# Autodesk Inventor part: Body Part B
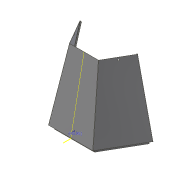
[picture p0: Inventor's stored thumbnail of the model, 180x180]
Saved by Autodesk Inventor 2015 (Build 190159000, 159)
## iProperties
Created: 2013-06
Part Number: Body Part B
Material: Steel, Mild
Document SubType Name: Sheet Metal
Designer: 1103005
Density: 1 g/cm^3
Sheet Metal Rule: Default_mm
Flat Pattern Width: 78.9104 cm
Flat Pattern Length: 65.539 cm
Flat Pattern Area: 5171.71 cm^2
Sheet Metal Width: 789.104 mm
Sheet Metal Length: 655.390 mm
Sheet Metal Area: 517171.389 mm^2
Appearance: Steel
Author: 1103005
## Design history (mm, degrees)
sketch "Sketch1"
  geometry: L1 (277.128, 0)-(138.564, -240); L2 (138.564, -240)-(-138.564, -240); L3 (-138.564, -240)-(-277.128, 0); 3 further points
  constraints: 6 end point, 2 horizontal alignment, 1 coincident, 1 midpoint, 1 vertical alignment, 6 other
  dimensions: "d0" = 240 distance from line of point (0, 0) L2
workplane "Work Plane1"
node "Lofted Flange1"
  sketch "Sketch2"
    geometry: L1 (-138.564, -240)-(-277.128, 0) reference; L2 (138.564, -240)-(-138.564, -240) reference; L3 (277.128, 0)-(138.564, -240) reference; L4 (-90.644, -157)-(-181.288, 0); L5 (181.288, 0)-(90.644, -157); L6 (90.644, -157)-(-90.644, -157); 3 further points
    constraints: 6 end point, 2 horizontal alignment, 1 coincident, 1 midpoint, 1 vertical alignment, 6 other
    dimensions: "d2" = 157 distance from line of point (0, 0) L6
sketch "Sketch13"
  geometry: L1 (0.589, -0.23)-(0, 0) reference; L2 (-155.822, 424.77)-(-238.822, -0.23) reference; L3 (-155.822, 424.77)-(-238.822, -0.23) reference; L4 (-286.704, 0)-(48.471, 0) reference
  dimensions: "Flange_Angle_1" = 78.9496 deg angle of L2 L4 (derived)
  node "Projected Loop1"
node "Flange6"
sketch "Sketch16"
  geometry: L1 (22.086, -274.868)-(22.086, 0) reference; L2 (22.086, 0)-(0, 0) reference; L3 (0, 0)-(0, -262.117) reference; L4 (22.086, -274.868)-(0, -262.117) reference; L5 (-59.178, -47.92)-(23.264, -0.322) reference; L6 (-371.411, -228.188)-(-453.853, -275.786) reference; L7 (-215.5, -386.536)-(-442.5, -255.477) reference; L8 (-442.5, -255.477)-(-454.264, -275.853); L9 (-430.589, -262.354)-(-454.264, -275.853); L10 (0, -13.754)-(23.528, 0); L11 (0, 0)-(23.528, 0); 1 further point
  constraints: 8 end point, 4 point on line, 1 horizontal, 1 other
extrude "Extrusion1" cut sketch "Sketch16" stored distance "d106" = 10; taper "d107" = 0 deg
node "Unfold1"
node "Flange10"
sketch "Sketch22"
  geometry: L1 (5.843, 432.74)-(5.843, 432.28) reference; L2 (0, 432.74)-(5.843, 432.74) reference; L3 (0, 0)-(0, 432.74) reference; L4 (5.843, 432.28)-(0, 430.987); L5 (0, 0)-(0, 432.74) reference; L6 (-126.727, 402.479)-(7.922, 432.28) reference; 1 further point
  constraints: 2 end point, 1 parallel, 1 point on line
cut "Cut3" sketch "Sketch22" dims "d144" = 1.2 (= Thickness), "d145" = 0
mirror "Mirror3"
mirror "Mirror4"
node "Refold1"
node "Flange8"
sketch "Sketch23"
  geometry: L1 (83.554, 224.895)-(1.2, 272.442) reference; L2 (-2.356, 274.546)-(-2.356, 270.364) reference; L3 (-2.356, 281.704)-(83.554, 224.895); L4 (-2.356, 270.364)-(-3.861, 270.364); L5 (-3.861, 270.364)-(-2.356, 281.704); 3 further points; 1 other entity
  constraints: 6 end point, 1 horizontal, 1 other
extrude "Extrusion4" cut sketch "Sketch23" stored distance "d146" = 0; taper "d147" = 0 deg
mirror "Mirror5"
sketch "Sketch24"
  geometry: 3 further points; 1 other entity
  constraints: 1 coincident, 1 other
hole "Hole2" sketch "Sketch24" at (13.533, 89.284) diameter "d148" = 7.5; stored, may be unused: countersink angle "d152" = 90 deg, drill point angle "d154" = 118 deg; dims "d149" = 6, "d150" = 4, "d151" = 2, "d153" = 1.2 (= Thickness)
pattern_circular "Circular Pattern2" dims angle "d156" = 120 deg
body "Solid1"
bend "Bend1" dims "d4" = 1.2 (= BendRadius), "d5" = 1.2 (= BendReliefWidth), "d6" = 0.6 (= BendReliefDepth), "d7" = 2.4 (= MinimumRemnant), "d8" = 1.2 (= BendRadius), "SeamGap" = 0.01, "Thickness" = 1.2
sketch "Sketch14"
  geometry: L1 through (-68.942, 119.411) direction (0.5, -0.866); L2 through (10.825, 6.25) direction (0.866, 0.5); L3 (21.651, 12.5)-(-116.233, 251.322); L4 (-116.233, 251.322)-(-137.884, 238.822)
  constraints: 6 end point, 1 perpendicular, 2 other
face "Plate6" dims "d86" = 1.2 (= BendReliefWidth), "d87" = 0.6 (= BendReliefDepth), "d88" = 2.4 (= MinimumRemnant), "d89" = 1.2 (= BendRadius), "d90" = 25, "d91" = 17.63663 (computed from Flange_Angle_1), "d92" = 1.2 (= BendRadius), "d93" = 4.8 (= CornerReliefSize), "d94" = 1, "d95" = 1.2 (= JacobiRadiusSize), "SeamGap" = 0.01, "Thickness" = 1.2
bend "Bend7" dims "d86" = 1.2 (= BendReliefWidth), "d87" = 0.6 (= BendReliefDepth), "d88" = 2.4 (= MinimumRemnant), "d89" = 1.2 (= BendRadius), "d90" = 25, "d91" = 17.63663 (computed from Flange_Angle_1), "d92" = 1.2 (= BendRadius), "SeamGap" = 0.01, "Thickness" = 1.2
feature "Corner6" dims "d90" = 25, "d91" = 17.63663 (computed from Flange_Angle_1), "d93" = 4.8 (= CornerReliefSize), "d94" = 1, "d95" = 1.2 (= JacobiRadiusSize)
node "Projected Loop2"
sketch "Sketch19"
  geometry: L1 through (124.182, 0) direction (-1, -4.29e-16); L2 through (0, -12.5) direction (3.59e-16, -1); L3 (0, -25)-(248.363, -25); L4 (248.363, -25)-(248.363, 0)
  constraints: 6 end point, 1 horizontal, 1 perpendicular, 1 vertical
face "Plate8" dims "d112" = 1.2 (= BendReliefWidth), "d113" = 0.6 (= BendReliefDepth), "d114" = 2.4 (= MinimumRemnant), "d115" = 1.2 (= BendRadius), "d116" = 25, "d117" = 90 deg, "d118" = 1.2 (= BendRadius), "d119" = 4.8 (= CornerReliefSize), "d120" = 1, "d121" = 1.2 (= JacobiRadiusSize), "SeamGap" = 0.01, "Thickness" = 1.2
bend "Bend9" dims "d112" = 1.2 (= BendReliefWidth), "d113" = 0.6 (= BendReliefDepth), "d114" = 2.4 (= MinimumRemnant), "d115" = 1.2 (= BendRadius), "d116" = 25, "d117" = 90 deg, "d118" = 1.2 (= BendRadius), "SeamGap" = 0.01, "Thickness" = 1.2
feature "Corner8" dims "d116" = 25, "d117" = 90 deg, "d119" = 4.8 (= CornerReliefSize), "d120" = 1, "d121" = 1.2 (= JacobiRadiusSize)
sketch "Sketch21"
  geometry: L1 through (47.595, 211.071) direction (-0.22, -0.976); L2 through (4.878, -1.1) direction (0.976, -0.22); L3 (9.755, -2.2)-(104.945, 419.941); L4 (104.945, 419.941)-(95.19, 422.141)
  constraints: 6 end point, 1 perpendicular, 2 other
face "Plate10" dims "d134" = 1.2 (= BendReliefWidth), "d135" = 0.6 (= BendReliefDepth), "d136" = 2.4 (= MinimumRemnant), "d137" = 1.2 (= BendRadius), "d138" = 10, "d139" = 120 deg, "d140" = 1.2 (= BendRadius), "d141" = 4.8 (= CornerReliefSize), "d142" = 1.2 (= GapSize), "d143" = 1.2 (= JacobiRadiusSize), "SeamGap" = 0.01, "Thickness" = 1.2
bend "Bend11" dims "d134" = 1.2 (= BendReliefWidth), "d135" = 0.6 (= BendReliefDepth), "d136" = 2.4 (= MinimumRemnant), "d137" = 1.2 (= BendRadius), "d138" = 10, "d139" = 120 deg, "d140" = 1.2 (= BendRadius), "SeamGap" = 0.01, "Thickness" = 1.2
feature "Corner10" dims "d138" = 10, "d139" = 120 deg, "d141" = 4.8 (= CornerReliefSize), "d142" = 1.2 (= GapSize), "d143" = 1.2 (= JacobiRadiusSize)
node "Reference2"
feature "Definition1"
other parameters: "BendRadius" = 1.2 (= Thickness), "BendReliefWidth" = 1.2 (= Thickness), "BendReliefDepth" = 0.6 (= 0.5 x Thickness), "CornerReliefSize" = 4.8 (= 4 x Thickness), "MinimumRemnant" = 2.4 (= 2 x Thickness), "TransitionRadius" = 1.2 (= BendRadius), "JacobiRadiusSize" = 1.2 (= BendRadius), "GapSize" = 1.2 (= Thickness), "d1" = 425, "d3" = 0.5, "BendRadius" = 1.2, "BendReliefDepth" = 0.6, "BendReliefWidth" = 1.2, "CornerReliefSize" = 4.8, "GapSize" = 1.2, "JacobiRadiusSize" = 1.2, "MinimumRemnant" = 2.4, "Thickness" = 1.2, "TransitionRadius" = 1.2, "Flange_Angle_1" = 13.7793
